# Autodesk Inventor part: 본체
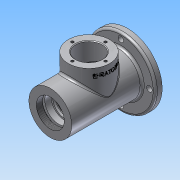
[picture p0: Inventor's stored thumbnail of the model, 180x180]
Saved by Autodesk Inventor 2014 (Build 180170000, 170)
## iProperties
Created: 2016-08
Part Number: 본체
Material: 알루미늄 6061
Document SubType Name: Modeling
Designer: NET
Mass: 729.523 g
Surface Area: 621.042 cm^2
Volume: 269.197 cm^3
Density: 2.71 g/cm^3
Appearance: 알루미늄 - 평지
Author: NET
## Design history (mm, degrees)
sketch "스케치1"
  geometry: L1 (0, 0)-(115, 0); L2 (115, 21)-(115, 31); L3 (112, 50)-(105, 50); L4 (0, 31)-(0, 0); L5 (115, 31)-(112, 31); L6 (112, 31)-(112, 50); L7 (102, 47)-(102, 31); L8 (102, 31)-(0, 31); L9 (9, 0)-(9, 24); L10 (9, 24)-(12, 24); L11 (12, 24)-(12, 20); L12 (12, 20)-(21, 20); L13 (21, 20)-(21, 17.5); L14 (21, 17.5)-(24.25, 17.5); L15 (24.25, 17.5)-(24.25, 18.5); L16 (24.25, 18.5)-(26, 18.5); L17 (26, 18.5)-(26, 17.5); L18 (26, 17.5)-(37, 17.5); L19 (37, 17.5)-(37, 23); L20 (40, 26)-(72, 26); L21 (75, 23)-(75, 17.5); L22 (75, 17.5)-(85.7, 17.5); L23 (86, 17.2)-(86, 16.5); L24 (86, 16.5)-(88, 16.5); L25 (91, 13.5)-(91, 10); L26 (91, 10)-(93.7, 10); L27 (93.7, 10)-(93.7, 12.2); L28 (94, 12.5)-(100.3, 12.5); L29 (101, 12.904)-(101, 13.886); L30 (102.991, 16.711)-(115, 21); L31 (100.3, 12.5)-(101, 12.904); L32 (56, 26)-(56, 31); A1 r 3 centre (105, 47) between (105, 50) and (102, 47); A2 r 3 centre (88, 13.5) between (91, 13.5) and (88, 16.5); A3 r 3 centre (104, 13.886) between (102.991, 16.711) and (101, 13.886); A4 r 0.3 centre (85.7, 17.2) between (86, 17.2) and (85.7, 17.5); A5 r 0.3 centre (94, 12.2) between (94, 12.5) and (93.7, 12.2); A6 r 3 centre (40, 23) between (40, 26) and (37, 23); A7 r 3 centre (72, 23) between (75, 23) and (72, 26); 7 further points
  constraints: 64 end point, 18 parallel, 15 point on line, 14 point on circle, 14 tangent, 11 perpendicular, 7 centre point, 3 equal radius, 2 midpoint, 1 horizontal, 1 horizontal alignment, 1 vertical alignment
  dimensions: "d0" = 115 distance of L1.start L1.end; "d1" = 62 diameter of L8 L1; "d2" = 100 diameter of L3 L1; "d3" = 3 distance of L2.end L5.end; "d4" = 13 distance between parallel lines of L2 L7; "d5" = 3 radius of A1; "d37" = 3 distance of L9.end L10.end; "d38" = 14 distance between parallel lines of L2 L29; "d39" = 7.3 distance between parallel lines of L27 L29; "d40" = 2.7 distance between parallel lines of L25 L27; "d41" = 5 distance between parallel lines of L23 L25; "d42" = 38 distance between parallel lines of L21 L19; "d43" = 33 diameter of L24 L1; "d44" = 35 diameter of L22 L1; "d45" = 35 diameter of L18 L1; "d46" = 52 diameter of L20 L1; "d47" = 32 diameter of point (101, 16) L1; "d48" = 25 diameter of L28 L1; "d49" = 20 diameter of L26 L1; "d50" = 48 diameter of L10 L1; "d51" = 40 diameter of L12 L1; "d52" = 35 diameter of L14 L1; "d53" = 12 distance between parallel lines of L4 L11; "d54" = 21 distance between parallel lines of L4 L13; "d55" = 26 distance between parallel lines of L4 L17; "d56" = 60 distance between parallel lines of L23 L17; "d57" = 1.75 distance of L15.end L16.end; "d58" = 37 diameter of L16 L1; "d60" = 86 distance between parallel lines of L4 L23 (derived); "d61" = 0.7 distance of L28.end point (101, 12.5); "d62" = 30 deg angle of L28 L31; "d63" = 42 diameter of L2.start L1; "d64" = 24 distance between parallel lines of L2 L25 (derived); "d65" = 3 radius of A2; "d66" = 0.3 radius of A4; "d80" = 56 distance between parallel lines of L4 L32; "d81" = 3 radius of A6
revolve "회전1" sketch "스케치1" stored, may be unused: angle "d6" = 90 deg
sketch "스케치2"
  geometry: C1 r 47 at (0, 0) reference; A1 r 41.5 centre (0, 0) between (41.5, 0) and (0, 41.5); 2 further points
  constraints: 4 point on circle, 1 centre point, 1 coincident
  dimensions: "d7" = 83 diameter of A1
hole "구멍1" sketch "스케치2" at (41.5, 0), (0, 41.5), (0, -41.5), (-41.5, 0) diameter "d8" = 8; stored, may be unused: countersink angle "d12" = 90 deg, drill point angle "d14" = 118 deg; dims "d9" = 6, "d10" = 4, "d11" = 2, "d13" = 8
node "작업 평면1"
sketch "스케치3"
  geometry: L1 (31, 0)-(-31, 0) reference; C1 r 30 at (0, 56); 2 further points
  constraints: 1 centre point, 1 midpoint, 1 vertical alignment
  dimensions: "d16" = 60 diameter of C1; "d17" = 56 distance from line of L1 C1.centre
extrude "돌출1" join sketch "스케치3" stored distance "d18" = 10; taper "d19" = 0 deg
sketch "스케치4"
  geometry: C1 r 30 at (0, 0) reference; A1 r 24 centre (0, 0) between (0, 24) and (-24, 0); 3 further points
  constraints: 4 point on circle, 1 centre point, 1 coincident
  dimensions: "d29" = 48 diameter of A1
hole "구멍3" sketch "스케치4" at (0, 24), (-24, 0), (0, -24), (24, 0) diameter "d30" = 4; stored, may be unused: countersink angle "d34" = 90 deg, drill point angle "d36" = 118 deg; dims "d31" = 6, "d32" = 40, "d33" = 2, "d35" = 10
node "작업 평면2"
sketch "스케치5"
  geometry: L1 (-56, -80)-(-56, -18) reference; L2 (-30, 0)-(30, 0) reference; 2 further points
  constraints: 1 other
  dimensions: "d67" = 56 distance from line of L1 point (0, -10); "d68" = 10 distance from line of L2 point (0, -10)
feature "엠보싱1" sketch "스케치5" dims "d69" = 0.5, "d70" = 0
feature "스레드1" dims "d71" = 8, "d72" = 0
feature "스레드2" dims "d73" = 8, "d74" = 0
feature "스레드3" dims "d75" = 8, "d76" = 0
feature "스레드4" dims "d77" = 8, "d78" = 0
fillet "모깎기1" dims "d79" = 3
hole "구멍4" diameter "d84" = 38; stored, may be unused: countersink angle "d88" = 90 deg, drill point angle "d90" = 118 deg; dims "d82" = 10, "d83" = 10, "d85" = 6, "d86" = 40, "d87" = 2, "d89" = 49
chamfer "모따기1" distance "d91" = 1; stored, may be unused: second distance "d92" = 2, angle "d93" = 45 deg
hole "구멍5" diameter "d96" = 40.376; stored, may be unused: countersink angle "d100" = 90 deg, drill point angle "d102" = 0 deg; dims "d94" = 10, "d95" = 10, "d97" = 9, "d98" = 4, "d99" = 2, "d101" = 9
node "솔리드1"
other parameters: "d15" = 49
